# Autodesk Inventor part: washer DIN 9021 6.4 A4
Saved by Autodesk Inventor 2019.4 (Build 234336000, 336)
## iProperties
Created: 2021-08
Part Number: washer DIN 9021 6.4 A4
Material: Generic
Document SubType Name: Modeling
Designer: Administrator
Density: 1 g/cm^3
Appearance: Default
Title: washer DIN 9021 6.4 A4
Author: Administrator
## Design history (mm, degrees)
feature "Body1"
body "Solid1"
